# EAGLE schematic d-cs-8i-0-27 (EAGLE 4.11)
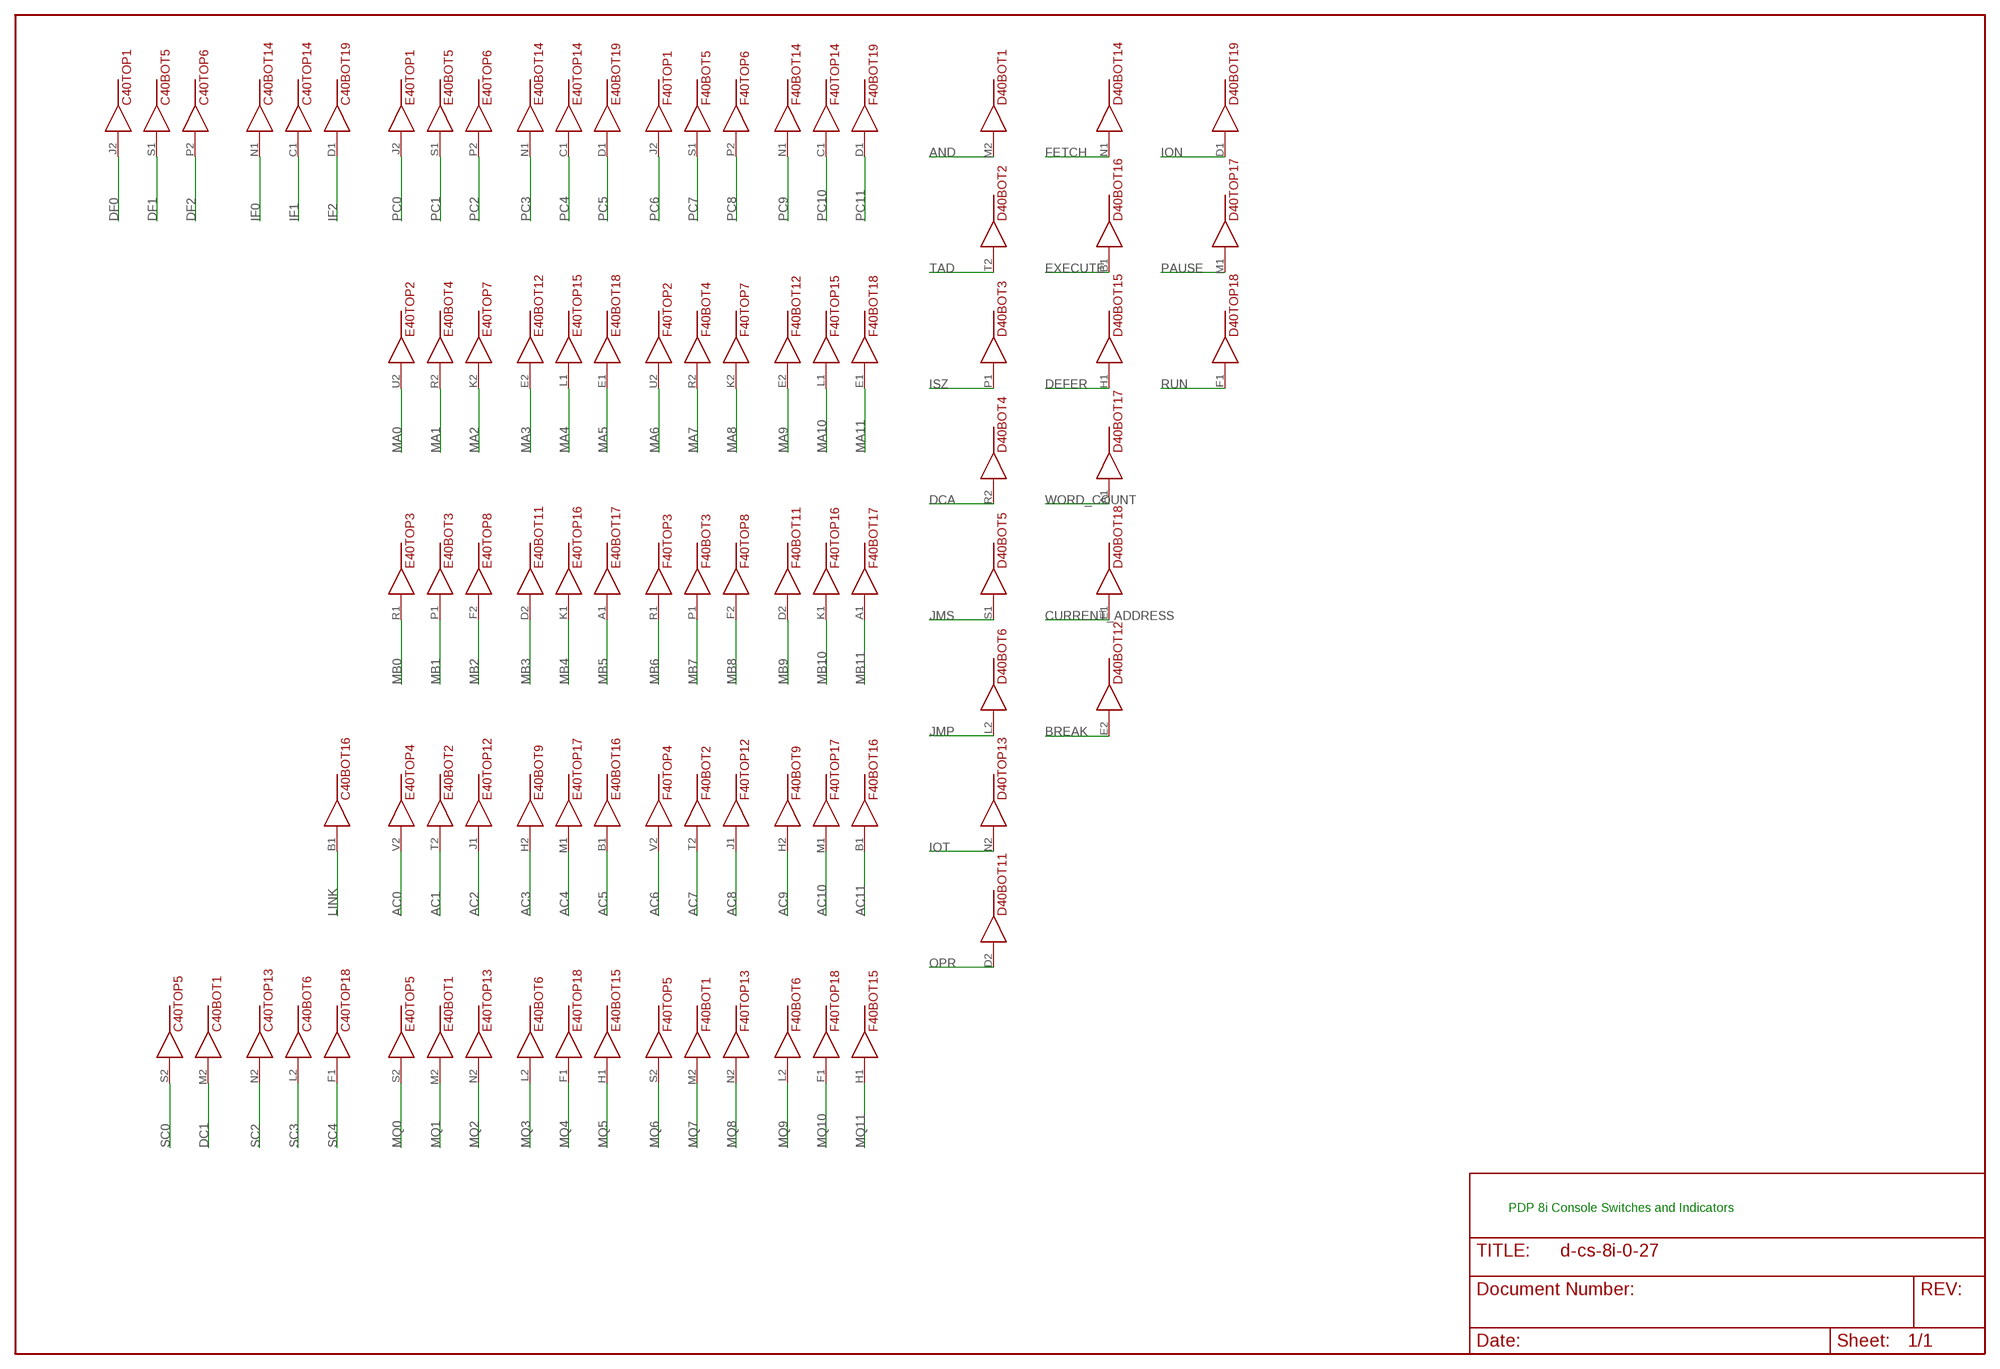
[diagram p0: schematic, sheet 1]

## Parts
C40  M900  [H807]
D40  M900  [H807]
E40  M900  [H807]
F40  M900  [H807]

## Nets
AC0: E40.V2
AC1: E40.T2
AC2: E40.J1
AC3: E40.H2
AC4: E40.M1
AC5: E40.B1
AC6: F40.V2
AC7: F40.T2
AC8: F40.J1
AC9: F40.H2
AC10: F40.M1
AC11: F40.B1
AND: D40.M2
BREAK: D40.E2
CURRENT_ADDRESS: D40.E1
DC1: C40.M2
DCA: D40.R2
DEFER: D40.H1
DF0: C40.J2
DF1: C40.S1
DF2: C40.P2
EXECUTE: D40.B1
FETCH: D40.N1
IF0: C40.N1
IF1: C40.C1
IF2: C40.D1
ION: D40.D1
IOT: D40.N2
ISZ: D40.P1
JMP: D40.L2
JMS: D40.S1
LINK: C40.B1
MA0: E40.U2
MA1: E40.R2
MA2: E40.K2
MA3: E40.E2
MA4: E40.L1
MA5: E40.E1
MA6: F40.U2
MA7: F40.R2
MA8: F40.K2
MA9: F40.E2
MA10: F40.L1
MA11: F40.E1
MB0: E40.R1
MB1: E40.P1
MB2: E40.F2
MB3: E40.D2
MB4: E40.K1
MB5: E40.A1
MB6: F40.R1
MB7: F40.P1
MB8: F40.F2
MB9: F40.D2
MB10: F40.K1
MB11: F40.A1
MQ0: E40.S2
MQ1: E40.M2
MQ2: E40.N2
MQ3: E40.L2
MQ4: E40.F1
MQ5: E40.H1
MQ6: F40.S2
MQ7: F40.M2
MQ8: F40.N2
MQ9: F40.L2
MQ10: F40.F1
MQ11: F40.H1
OPR: D40.D2
PAUSE: D40.M1
PC0: E40.J2
PC1: E40.S1
PC2: E40.P2
PC3: E40.N1
PC4: E40.C1
PC5: E40.D1
PC6: F40.J2
PC7: F40.S1
PC8: F40.P2
PC9: F40.N1
PC10: F40.C1
PC11: F40.D1
RUN: D40.F1
SC0: C40.S2
SC2: C40.N2
SC3: C40.L2
SC4: C40.F1
TAD: D40.T2
WORD_COUNT: D40.A1
Unconnected: C40.A1 C40.D2 C40.E1 C40.E2 C40.F2 C40.H1 C40.H2 C40.J1 C40.K1 C40.K2 C40.L1 C40.M1 C40.P1 C40.R1 C40.R2 C40.T2 C40.U2 C40.V2 D40.C1 D40.F2 D40.H2 D40.J1 D40.J2 D40.K1 D40.K2 D40.L1 D40.P2 D40.R1 D40.S2 D40.U2 D40.V2

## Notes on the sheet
- PDP 8i Console Switches and Indicators

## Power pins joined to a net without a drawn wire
GND: C40.C2(GND) C40.T1(GND) D40.C2(GND) D40.T1(GND) E40.C2(GND) E40.T1(GND) F40.C2(GND) F40.T1(GND)
VCC: C40.A2(VCC) D40.A2(VCC) E40.A2(VCC) F40.A2(VCC)

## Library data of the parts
C40 D40 E40 F40 = dec-m:M900

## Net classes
1 Supply: width 0.762 mm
